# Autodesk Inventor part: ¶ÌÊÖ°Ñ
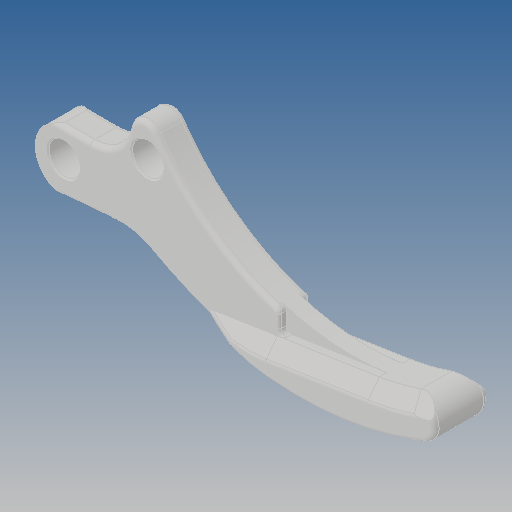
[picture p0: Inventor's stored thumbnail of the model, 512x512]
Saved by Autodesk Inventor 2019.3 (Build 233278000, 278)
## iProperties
Created: 2017-12
Part Number: ¶ÌÊÖ°Ñ
Material: Ogólny
Document SubType Name: Modeling
Designer: Admin
Density: 1 g/cm^3
Appearance: Domyślna
Author: Admin
Revision Number: ÈÎºÎ
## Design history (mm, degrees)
feature "Ô²½Ç49"
node "Bryła1"
